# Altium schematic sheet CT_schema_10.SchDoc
size 274 x 160 mm
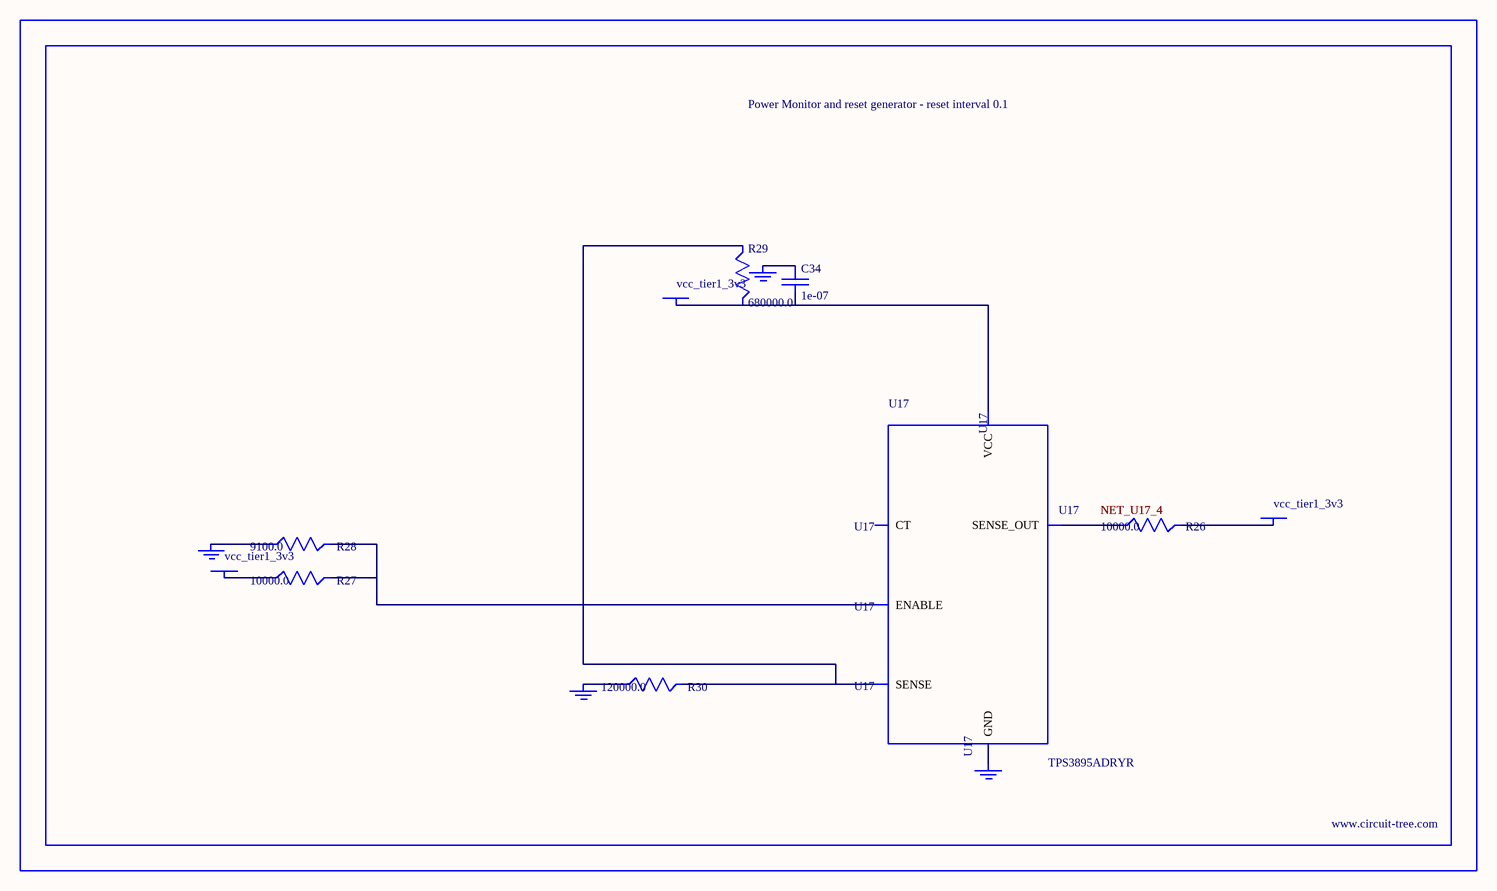
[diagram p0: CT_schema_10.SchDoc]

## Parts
BORDER9  (no value)
C34  1e-07  [C0402]
GND_INSTANCE_9_0  (no value)
GND_INSTANCE_9_1  (no value)
GND_INSTANCE_9_2  (no value)
GND_INSTANCE_9_3  (no value)
POWER_INSTANCE_9_0  vcc_tier1_3v3
POWER_INSTANCE_9_1  vcc_tier1_3v3
POWER_INSTANCE_9_2  vcc_tier1_3v3
R26  10000.0  [R0603]
R27  10000.0  [R0603]
R28  9100.0  [R0603]
R29  680000.0  [R0603]
R30  120000.0  [R0603]
U17  TPS3895ADRYR  [SON-6]

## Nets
NetC34_1: C34.1 GND_INSTANCE_9_2.0(GND)
NetC34_2: C34.2 POWER_INSTANCE_9_2.0(PWR) R29.2 U17.6(VCC)
NetGND_INSTANCE_9_0_0: GND_INSTANCE_9_0.0(GND) R28.1
NetGND_INSTANCE_9_1_0: GND_INSTANCE_9_1.0(GND) R30.1
NetGND_INSTANCE_9_3_0: GND_INSTANCE_9_3.0(GND) U17.2(GND)
NetPOWER_INSTANCE_9_0_0: POWER_INSTANCE_9_0.0(PWR) R27.1
NetPOWER_INSTANCE_9_1_0: POWER_INSTANCE_9_1.0(PWR) R26.2
NetR26_1: R26.1 U17.4(SENSE_OUT)
NetR27_2: R27.2 R28.2 U17.1(ENABLE)
NetR29_1: R29.1 R30.2 U17.3(SENSE)

Not connected (* = marked no-connect by the designer): U17 5(CT)

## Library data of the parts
BORDER9 = BORDER_PAGE9
C34 = C0402C104K3RACTU
GND_INSTANCE_9_0-GND_INSTANCE_9_3 = GND
POWER_INSTANCE_9_0-POWER_INSTANCE_9_2 = PWR
R26 R27 = RC0603JR-0710KL
R28 = RC0603JR-079K1L
R29 = RC0603JR-07680KL
R30 = RC0603JR-07120KL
